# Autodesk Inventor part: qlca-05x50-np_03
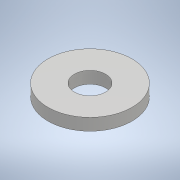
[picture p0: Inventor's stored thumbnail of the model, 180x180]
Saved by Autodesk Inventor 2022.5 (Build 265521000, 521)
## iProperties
Part Number: qlca-05x50-np_03
Material: 一般
Document SubType Name: Modeling
Designer: ImaoCorp
Density: 1 g/cm^3
Appearance: 既定
Author: ImaoCorp
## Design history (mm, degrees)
feature "qlca-05x50-np_03"
node "ソリッド1"
